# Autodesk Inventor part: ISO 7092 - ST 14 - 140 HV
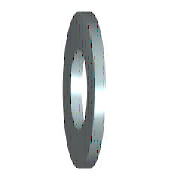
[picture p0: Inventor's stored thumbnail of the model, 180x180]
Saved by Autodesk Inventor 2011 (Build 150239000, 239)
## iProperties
IsCustomPart: 0
Created: 2009-02
Part Number: ISO 7092 - ST 14 - 140 HV
Material: Stainless Steel
Description: Plain washers-Small series-Product grade A
Document SubType Name: Modeling
Standard: ISO 7092
Designer: 904Chiaki
Standard Revision: Second edition 2000-06-01
Standards Organization: ISO
Language: en-US
Size Designation: ST 14 - 140 HV
Categories: <MemberInstance><Categories><Category DisplayName="Fasteners" InternalName="e4da775c-781d-43d5-af7c-5136215cf5a6" Mnemonic="FSTN"><Category DisplayName="Washers
Density: 8.08 g/cm^3
Mass: 5.56863 g
Surface Area: 8.57655 cm^2
Volume: 0.689187 cm^3
Author: 904Chiaki
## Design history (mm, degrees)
body "Solid1"
sketch "Sketch"
  geometry: C1 r 12 at (0, 0); C2 r 7.5 at (0, 0); 1 further point
  constraints: 2 centre point, 2 coincident
  dimensions: "d0" = 15 diameter of C2 (= SD1); "d1" = 24 diameter of C1 (= SD2)
extrude "Body" new body sketch "Sketch" distance "d2" = 2.5 (= SD); taper "d3" = 0 deg
workaxis "Work Axis1"
workplane "Work Plane1"
other parameters: "SD1" = 15 [user parameter; used in 1 equation term], "SD2" = 24 [user parameter; used in 1 equation term], "SD" = 2.5 [user parameter; used in 1 equation term], "d4" = 0, "d5" = 0, "d6" = 0, "d7" = 0, "NND" = 14 [user parameter]
